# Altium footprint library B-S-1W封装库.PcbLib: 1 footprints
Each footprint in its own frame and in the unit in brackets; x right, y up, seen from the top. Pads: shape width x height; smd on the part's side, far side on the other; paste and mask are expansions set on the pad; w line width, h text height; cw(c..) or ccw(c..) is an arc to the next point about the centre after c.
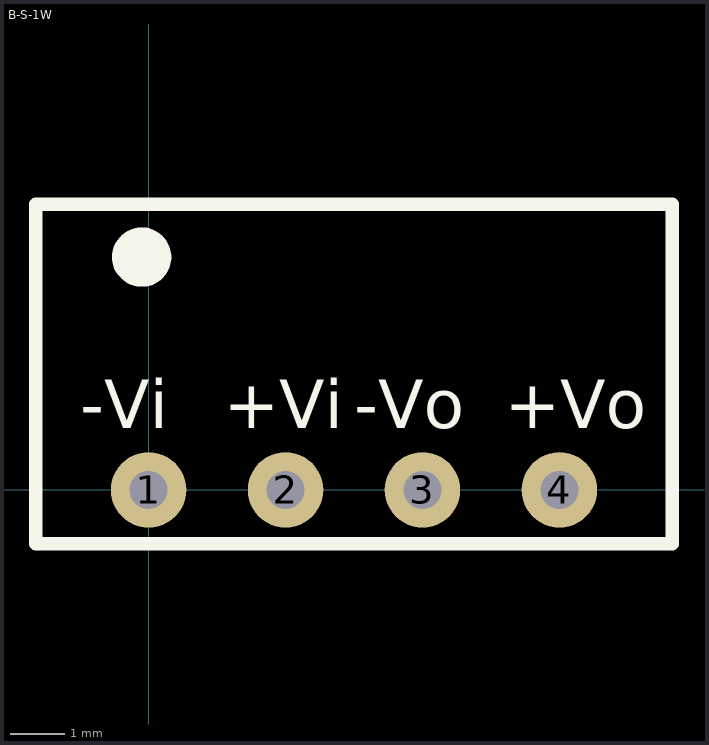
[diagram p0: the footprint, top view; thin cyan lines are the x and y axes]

## B-S-1W [mm]
pads (4):
  round 1.4 hole 0.7: 1(0,0) 2(2.54,0) 3(5.08,0) 4(7.62,0)
Top Overlay:
  circle w0.6: c-0.127,4.318 r0.25
  lines w0.254: -2.09,-1 9.71,-1 9.71,5.3 -2.09,5.3 -2.09,-1
  text "-Vi" at -1.27,1.143 h0.9
  text "+Vi" at 1.397,1.143 h0.9
  text "-Vo" at 3.81,1.143 h0.9
  text "+Vo" at 6.604,1.143 h0.9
